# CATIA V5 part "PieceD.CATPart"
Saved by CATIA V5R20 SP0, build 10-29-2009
Part number: PieceD
Bounding box of the stored display mesh (mm): x -20.997 to 20.997, y -20.998 to 20.998, z -63 to 10
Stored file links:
  D:\Dropbox\IAO\IAO_2010\iao\IAO Reviser CAO\Problemes\IAO_2010_1447_melguidj\Catia_1447_melguidj\PieceD.CATPart
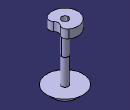
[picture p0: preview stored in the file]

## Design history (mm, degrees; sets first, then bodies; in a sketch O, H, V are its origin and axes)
Body1 (main body)
  Sketch1 on xy-plane, origin (0, 0, 0), H (1, 0, 0), V (0, 1, 0)
    point P1 (0, 0)
    point P2 (0, -12.5)
    circle A1 centre (0, 0) radius 4
    arc A2 centre (0, 0) radius 15 from (8, 12.6886) to (8, -12.6886) ccw
    axis line L1 (16.2484, 7.4881) -> (13.1511, 9.4409)
    point P5 (8, 12.6886)
    point P6 (8, -12.6886)
    arc A3 centre (4.8, 7.6131) radius 6 from (8, 12.6886) to (9.4379, 3.8066) cw
    arc A4 centre (14.0758, 0) radius 6 from (9.4379, 3.8066) to (9.4379, -3.8066) ccw
    arc A5 centre (4.8, -7.6131) radius 6 from (9.4379, -3.8066) to (8, -12.6886) cw
    point P12 (8, -12.6886)
    radius A1 = 4
    radius A2 = 15
    radius A3 = 6
    radius A4 = 6
    radius A5 = 6
    distance P5 V = 8
    distance P6 V = 8
    coincidence: P1 V, P2 V, P1 O, L1 P5, A5 P12, P12 A2
    tangency: L1 A2, A3 A2, A4 A3, A5 A4, A5 A2
    concentricity: A2 A1
  Pad1: profile Sketch1, direction (0, 0, 1), length 10
  Sketch2 on start face of Pad1, origin (0, 0, 0), H (1, 0, 0), V (0, -1, 0)
    circle A1 centre (0, 0) radius 4
    reference projected circle E1 centre (0, 0) radius 4 from edge [face of Pad1 from Sketch1.A1 | start face of Pad1]
    coincidence: A1 E1
  Pad2: profile Sketch2, direction (0, 0, -1), length 45
  Plane1: stored without definition
  DatumCurve1
  DatumCurve2
  Sketch3 on Plane1, origin (0, 0, 0), H (-0.2368, -0.9715, 0), V (0, 0, 1)
    point P1 (0, -26.0088)
    line L1 (0, -26.0088) -> (0, -63)
    line L2 (0, -63) -> (-14, -63)
    line L3 (-14, -63) -> (-21, -56)
    line L4 (-21, -56) -> (-4, -56)
    line L5 (-4, -56) -> (-4, -26.0088)
    line L6 (-4, -26.0088) -> (0, -26.0088)
    reference projected line E1 through (0, -77) direction (1, 0) from edge of DatumCurve2
    length L6 = 4
    angle L3 L2 = 45
    distance L2 E1 = 14
    distance L2 L4 = 7
    length L2 = 14
    coincidence: P1 V
    vertical: L1 V, L5 V
    horizontal: L2 H, L4 H, L6 H
  Shaft1: profile Sketch3, axis Sketch3.L1, angle 360
  Plane2: type Offset, RefPlane end face of Pad1, Offset 10
  Sketch4 on Plane2, origin (0, 0, 0), H (1, 0, 0), V (0, -1, 0)
    projected arc E1 centre (0, 0) radius 15 from (8, 12.6886) to (8, -12.6886) ccw from edge [face of Pad1 from Sketch1.A2 | end face of Pad1]
    projected arc E2 centre (4.8, -7.6131) radius 6 from (8, -12.6886) to (9.4379, -3.8066) ccw from edge [face of Pad1 from Sketch1.A3 | end face of Pad1]
    projected arc E3 centre (14.0758, 0) radius 6 from (9.4379, 3.8066) to (9.4379, -3.8066) ccw from edge [face of Pad1 from Sketch1.A4 | end face of Pad1]
    projected arc E4 centre (4.8, 7.6131) radius 6 from (9.4379, 3.8066) to (8, 12.6886) ccw from edge [face of Pad1 from Sketch1.A5 | end face of Pad1]
  Sketch5 on start face of Pad1, origin (0, 0, 0), H (1, 0, 0), V (0, -1, 0)
    projected arc E1 centre (0, 0) radius 15 from (8, 12.6886) to (8, -12.6886) ccw from edge [start face of Pad1 | face of Pad1 from Sketch1.A2]
    projected arc E2 centre (4.8, 7.6131) radius 6 from (9.4379, 3.8066) to (8, 12.6886) ccw from edge [start face of Pad1 | face of Pad1 from Sketch1.A5]
    projected arc E3 centre (14.0758, 0) radius 6 from (9.4379, 3.8066) to (9.4379, -3.8066) ccw from edge [start face of Pad1 | face of Pad1 from Sketch1.A4]
    projected arc E4 centre (4.8, -7.6131) radius 6 from (8, -12.6886) to (9.4379, -3.8066) ccw from edge [start face of Pad1 | face of Pad1 from Sketch1.A3]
